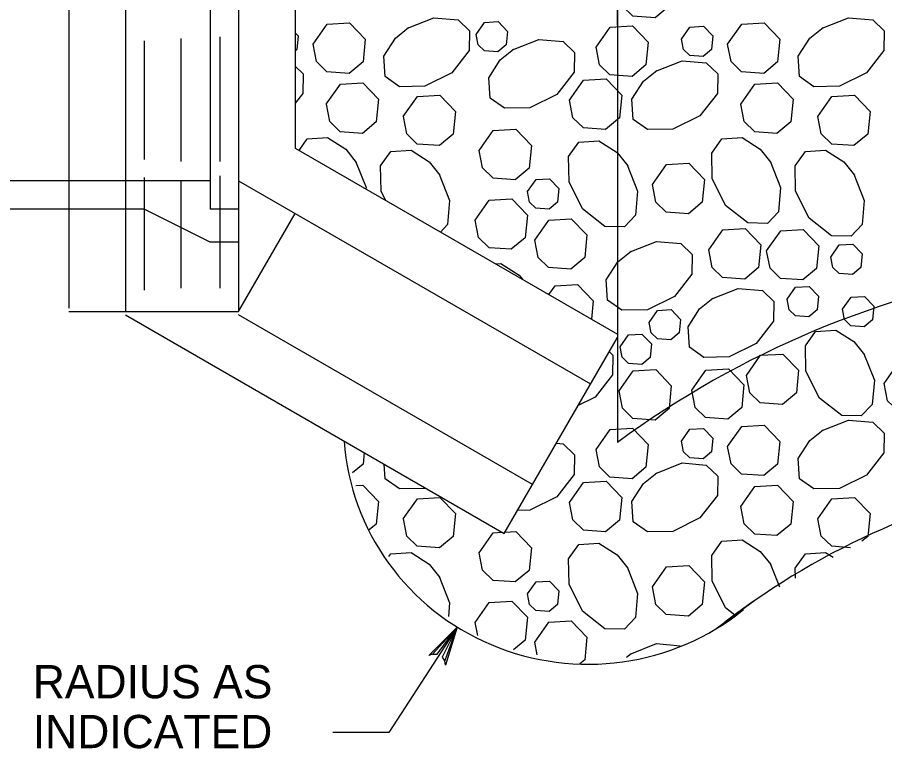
# Model space of a CAD drawing. Extents: x 636183 to 639890, y 299162 to 300538.
# Drawn here: x 638288.4 to 638366.6, y 299728.5 to 299794.5 of the extents above; entities that cross this region are included whole.
import ezdxf

# ---------------------------------------------------------------- set-up
doc = ezdxf.new("R2010")
doc.units = 0
doc.layers.add('Default', color=7, linetype='Continuous')

msp = doc.modelspace()

# ---------------------------------------------------------------- linework, layer by layer
at = {"layer": 'Default'}
for p, q in [((638342.479, 299793.775), (638342.479, 299831.402)), ((638342.479, 299821.642), (638342.479, 299765.907)), ((638293.003, 299819.284), (638293.003, 299768.259)), ((638298.106, 299819.586), (638298.106, 299767.957)), ((638308.311, 299819.586), (638308.311, 299767.957)), ((638308.311, 299813.345), (638308.311, 299774.198)), ((638305.757, 299810.356), (638305.757, 299777.187)), ((638313.413, 299804.859), (638313.413, 299782.689)), ((638342.479, 299793.775), (638342.479, 299756.147)), ((638306.61, 299792.726), (638306.61, 299781.487)), ((638299.806, 299792.377), (638299.806, 299781.65)), ((638303.111, 299792.563), (638303.111, 299781.487)), ((638313.413, 299782.689), (638342.479, 299765.907)), ((638306.61, 299780.185), (638306.61, 299770.064)), ((638305.757, 299779.741), (638263.016, 299779.741)), ((638299.806, 299780.045), (638299.806, 299769.878)), ((638303.111, 299779.766), (638303.111, 299770.064)), ((638308.311, 299779.741), (638340.059, 299761.414)), ((638298.106, 299777.187), (638261.142, 299777.187)), ((638299.779, 299777.187), (638298.106, 299777.187)), ((638305.757, 299774.198), (638299.779, 299777.187)), ((638308.311, 299777.187), (638305.757, 299777.187)), ((638308.311, 299767.957), (638313.413, 299776.795)), ((638308.311, 299774.198), (638305.757, 299774.198)), ((638293.003, 299767.957), (638308.311, 299767.957)), ((638298.106, 299767.656), (638332.272, 299747.931)), ((638334.823, 299752.348), (638308.311, 299767.656)), ((638332.272, 299747.931), (638342.479, 299765.606)), ((638354.872, 299741.885), (638351.469, 299739.382))]:
    msp.add_line(p, q, dxfattribs=at)
for points in [[(638342.633, 299797.075), (638343.904, 299798.882), (638345.933, 299798.998), (638347.342, 299797.536), (638347.138, 299795.487), (638345.885, 299794.445), (638343.882, 299794.59), (638342.94, 299795.504), (638342.635, 299797.074)], [(638323.553, 299793.503), (638325.931, 299794.445), (638328.114, 299794.257), (638329.151, 299793.27), (638329.119, 299791.498), (638327.544, 299789.485), (638325.11, 299788.268), (638322.815, 299788.228), (638321.525, 299789.146), (638321.402, 299790.972), (638322.45, 299792.607), (638323.65, 299793.564)], [(638360.947, 299793.503), (638363.325, 299794.445), (638365.507, 299794.257), (638366.545, 299793.27), (638366.513, 299791.498), (638364.938, 299789.485), (638362.504, 299788.268), (638360.209, 299788.228), (638358.919, 299789.146), (638358.796, 299790.972), (638359.844, 299792.607), (638361.044, 299793.564)], [(638315.028, 299792.058), (638316.298, 299793.865), (638318.327, 299793.981), (638319.737, 299792.519), (638319.533, 299790.47), (638318.28, 299789.428), (638316.278, 299789.573), (638315.335, 299790.486), (638315.029, 299792.058)], [(638329.73, 299792.943), (638330.493, 299794.028), (638331.71, 299794.097), (638332.556, 299793.22), (638332.434, 299791.991), (638331.682, 299791.365), (638330.48, 299791.452), (638329.915, 299792.001), (638329.731, 299792.943)], [(638340.55, 299791.783), (638341.82, 299793.59), (638343.848, 299793.707), (638345.259, 299792.244), (638345.055, 299790.195), (638343.802, 299789.153), (638341.799, 299789.299), (638340.857, 299790.212), (638340.55, 299791.783)], [(638348.258, 299792.526), (638349.021, 299793.61), (638350.238, 299793.68), (638351.084, 299792.802), (638350.961, 299791.574), (638350.21, 299790.948), (638349.007, 299791.035), (638348.442, 299791.583), (638348.259, 299792.526)], [(638352.422, 299792.058), (638353.692, 299793.865), (638355.721, 299793.981), (638357.131, 299792.519), (638356.927, 299790.47), (638355.674, 299789.428), (638353.671, 299789.573), (638352.728, 299790.486), (638352.423, 299792.058)], [(638313.413, 299793.09), (638313.69, 299792.802), (638313.568, 299791.574), (638313.413, 299791.445)], [(638333.022, 299791.551), (638335.399, 299792.493), (638337.582, 299792.305), (638338.62, 299791.319), (638338.587, 299789.547), (638337.012, 299787.534), (638334.579, 299786.317), (638332.284, 299786.277), (638330.994, 299787.194), (638330.871, 299789.021), (638331.919, 299790.656), (638333.119, 299791.613)], [(638345.935, 299789.63), (638348.311, 299790.572), (638350.495, 299790.383), (638351.532, 299789.397), (638351.499, 299787.625), (638349.924, 299785.613), (638347.49, 299784.396), (638345.197, 299784.355), (638343.905, 299785.272), (638343.783, 299787.1), (638344.831, 299788.734), (638346.031, 299789.691)], [(638313.413, 299790.087), (638314.138, 299789.397), (638314.105, 299787.625), (638313.413, 299786.741)], [(638338.159, 299787.002), (638339.43, 299788.809), (638341.458, 299788.925), (638342.868, 299787.463), (638342.664, 299785.414), (638341.411, 299784.372), (638339.408, 299784.517), (638338.466, 299785.431), (638338.16, 299787.002)], [(638316.224, 299786.647), (638317.494, 299788.455), (638319.522, 299788.57), (638320.932, 299787.108), (638320.728, 299785.06), (638319.475, 299784.018), (638317.473, 299784.162), (638316.531, 299785.076), (638316.225, 299786.647)], [(638353.618, 299786.647), (638354.888, 299788.455), (638356.916, 299788.57), (638358.326, 299787.108), (638358.122, 299785.06), (638356.869, 299784.018), (638354.867, 299784.162), (638353.925, 299785.076), (638353.619, 299786.647)], [(638323.17, 299785.541), (638324.44, 299787.347), (638326.468, 299787.464), (638327.878, 299786.002), (638327.674, 299783.953), (638326.421, 299782.91), (638324.419, 299783.056), (638323.477, 299783.969), (638323.171, 299785.54)], [(638360.564, 299785.541), (638361.834, 299787.347), (638363.862, 299787.464), (638365.272, 299786.002), (638365.068, 299783.953), (638363.815, 299782.91), (638361.813, 299783.056), (638360.871, 299783.969), (638360.565, 299785.54)], [(638330.012, 299782.467), (638331.283, 299784.275), (638333.311, 299784.39), (638334.721, 299782.928), (638334.517, 299780.88), (638333.264, 299779.837), (638331.261, 299779.982), (638330.319, 299780.897), (638330.013, 299782.467)], [(638313.768, 299782.484), (638314.51, 299783.528), (638316.337, 299783.65), (638317.971, 299782.603), (638318.928, 299781.403)], [(638343.348, 299781.191), (638344.291, 299778.815), (638344.102, 299776.631), (638343.116, 299775.593), (638341.344, 299775.627), (638339.332, 299777.201), (638338.114, 299779.635), (638338.074, 299781.929), (638338.991, 299783.22), (638340.819, 299783.342), (638342.453, 299782.295), (638343.41, 299781.095)], [(638356.261, 299781.498), (638357.204, 299779.122), (638357.015, 299776.938), (638356.028, 299775.901), (638354.256, 299775.934), (638352.244, 299777.509), (638351.027, 299779.943), (638350.986, 299782.236), (638351.904, 299783.528), (638353.731, 299783.65), (638355.365, 299782.603), (638356.322, 299781.403)], [(638321.571, 299777.979), (638321.166, 299778.79), (638321.125, 299781.084), (638322.043, 299782.375), (638323.869, 299782.497), (638325.504, 299781.45), (638326.461, 299780.25)], [(638363.793, 299780.346), (638364.735, 299777.969), (638364.547, 299775.786), (638363.561, 299774.748), (638361.789, 299774.781), (638359.776, 299776.356), (638358.559, 299778.79), (638358.519, 299781.084), (638359.436, 299782.375), (638361.263, 299782.497), (638362.898, 299781.45), (638363.855, 299780.25)], [(638318.868, 299781.498), (638319.81, 299779.122), (638319.799, 299779.002)], [(638345.631, 299779.393), (638346.901, 299781.201), (638348.93, 299781.316), (638350.341, 299779.854), (638350.137, 299777.806), (638348.884, 299776.764), (638346.88, 299776.908), (638345.938, 299777.822), (638345.632, 299779.393)], [(638326.4, 299780.346), (638327.342, 299777.969), (638327.154, 299775.786), (638326.522, 299775.121)], [(638334.377, 299778.764), (638335.14, 299779.849), (638336.357, 299779.919), (638337.203, 299779.041), (638337.081, 299777.811), (638336.329, 299777.186), (638335.127, 299777.274), (638334.562, 299777.822), (638334.378, 299778.764)], [(638329.657, 299776.192), (638330.927, 299777.999), (638332.955, 299778.115), (638334.365, 299776.653), (638334.161, 299774.603), (638332.908, 299773.561), (638330.905, 299773.707), (638329.963, 299774.62), (638329.658, 299776.191)], [(638335.025, 299774.397), (638336.296, 299776.204), (638338.323, 299776.32), (638339.734, 299774.859), (638339.53, 299772.809), (638338.277, 299771.767), (638336.274, 299771.912), (638335.332, 299772.826), (638335.026, 299774.397)], [(638350.716, 299773.502), (638351.986, 299775.309), (638354.014, 299775.425), (638355.424, 299773.963), (638355.22, 299771.914), (638353.967, 299770.872), (638351.965, 299771.017), (638351.023, 299771.93), (638350.717, 299773.501)], [(638355.942, 299773.424), (638357.212, 299775.232), (638359.241, 299775.348), (638360.651, 299773.885), (638360.447, 299771.837), (638359.194, 299770.795), (638357.191, 299770.94), (638356.249, 299771.854), (638355.943, 299773.424)], [(638343.629, 299773.336), (638346.005, 299774.278), (638348.189, 299774.089), (638349.227, 299773.103), (638349.194, 299771.331), (638347.618, 299769.319), (638345.184, 299768.102), (638342.891, 299768.061), (638341.599, 299768.978), (638341.477, 299770.806), (638342.525, 299772.44), (638343.724, 299773.397)], [(638361.723, 299772.867), (638362.485, 299773.951), (638363.703, 299774.02), (638364.548, 299773.143), (638364.425, 299771.914), (638363.674, 299771.289), (638362.472, 299771.376), (638361.906, 299771.924), (638361.723, 299772.866)], [(638331.505, 299772.243), (638331.98, 299772.275), (638333.614, 299771.227), (638333.912, 299770.854)], [(638336.307, 299769.471), (638336.861, 299770.259), (638338.889, 299770.374), (638340.299, 299768.912), (638340.135, 299767.261)], [(638351.002, 299769.091), (638353.379, 299770.033), (638355.562, 299769.844), (638356.601, 299768.857), (638356.568, 299767.086), (638354.992, 299765.072), (638352.558, 299763.856), (638350.265, 299763.815), (638348.973, 299764.733), (638348.851, 299766.56), (638349.898, 299768.194), (638351.098, 299769.151)], [(638357.79, 299769.053), (638358.553, 299770.138), (638359.77, 299770.208), (638360.616, 299769.33), (638360.494, 299768.101), (638359.742, 299767.475), (638358.54, 299767.563), (638357.975, 299768.111), (638357.791, 299769.053)], [(638362.795, 299768.16), (638363.557, 299769.244), (638364.774, 299769.314), (638365.621, 299768.436), (638365.498, 299767.208), (638364.747, 299766.582), (638363.545, 299766.669), (638362.979, 299767.217), (638362.795, 299768.159)], [(638345.339, 299766.969), (638346.102, 299768.053), (638347.319, 299768.122), (638348.165, 299767.245), (638348.043, 299766.016), (638347.29, 299765.391), (638346.089, 299765.478), (638345.524, 299766.026), (638345.34, 299766.969)], [(638364.715, 299764.128), (638365.658, 299761.752), (638365.469, 299759.568), (638364.482, 299758.531), (638362.71, 299758.564), (638360.697, 299760.139), (638359.481, 299762.573), (638359.44, 299764.866), (638360.358, 299766.158), (638362.185, 299766.28), (638363.819, 299765.233), (638364.776, 299764.033)], [(638342.718, 299764.764), (638343.481, 299765.849), (638344.698, 299765.918), (638345.543, 299765.041), (638345.421, 299763.812), (638344.669, 299763.186), (638343.467, 299763.273), (638342.902, 299763.821), (638342.719, 299764.764)], [(638341.743, 299764.332), (638342.076, 299764.016), (638342.042, 299762.244), (638340.467, 299760.231), (638338.932, 299759.463)], [(638354.116, 299762.192), (638355.386, 299764), (638357.414, 299764.116), (638358.825, 299762.653), (638358.621, 299760.605), (638357.367, 299759.562), (638355.365, 299759.708), (638354.423, 299760.622), (638354.117, 299762.192)], [(638366.545, 299761.463), (638367.816, 299763.27), (638369.845, 299763.386), (638371.254, 299761.924), (638371.05, 299759.875), (638369.797, 299758.833), (638367.794, 299758.978), (638366.852, 299759.891), (638366.547, 299761.463)], [(638342.633, 299760.793), (638343.904, 299762.599), (638345.933, 299762.716), (638347.342, 299761.254), (638347.138, 299759.204), (638345.885, 299758.162), (638343.882, 299758.308), (638342.94, 299759.221), (638342.635, 299760.792)], [(638349.188, 299760.867), (638350.459, 299762.674), (638352.487, 299762.79), (638353.897, 299761.328), (638353.693, 299759.279), (638352.44, 299758.237), (638350.437, 299758.382), (638349.495, 299759.296), (638349.19, 299760.866)], [(638352.422, 299755.775), (638353.692, 299757.583), (638355.721, 299757.698), (638357.131, 299756.236), (638356.927, 299754.188), (638355.674, 299753.146), (638353.671, 299753.29), (638352.728, 299754.204), (638352.423, 299755.775)], [(638360.947, 299757.22), (638363.325, 299758.162), (638365.507, 299757.974), (638366.545, 299756.988), (638366.513, 299755.216), (638364.938, 299753.202), (638362.504, 299751.985), (638360.209, 299751.946), (638358.919, 299752.863), (638358.796, 299754.69), (638359.844, 299756.324), (638361.044, 299757.281)], [(638340.55, 299755.5), (638341.82, 299757.308), (638343.848, 299757.424), (638345.259, 299755.961), (638345.055, 299753.913), (638343.802, 299752.871), (638341.799, 299753.016), (638340.857, 299753.93), (638340.55, 299755.5)], [(638348.258, 299756.244), (638349.021, 299757.328), (638350.238, 299757.398), (638351.084, 299756.52), (638350.961, 299755.291), (638350.21, 299754.666), (638349.007, 299754.753), (638348.442, 299755.301), (638348.259, 299756.243)], [(638336.975, 299756.075), (638337.582, 299756.023), (638338.62, 299755.036), (638338.587, 299753.265), (638337.012, 299751.251), (638334.579, 299750.034), (638333.475, 299750.015)], [(638319.636, 299755.226), (638319.533, 299754.188), (638318.589, 299753.403)], [(638325.184, 299752.023), (638325.11, 299751.985), (638322.815, 299751.946), (638321.525, 299752.863), (638321.436, 299754.187)], [(638345.935, 299753.348), (638348.311, 299754.29), (638350.495, 299754.101), (638351.532, 299753.114), (638351.499, 299751.343), (638349.924, 299749.33), (638347.49, 299748.113), (638345.197, 299748.072), (638343.905, 299748.99), (638343.783, 299750.817), (638344.831, 299752.451), (638346.031, 299753.408)], [(638318.891, 299752.252), (638319.522, 299752.288), (638320.932, 299750.826), (638320.728, 299748.777), (638320.102, 299748.256)], [(638338.159, 299750.719), (638339.43, 299752.527), (638341.458, 299752.643), (638342.868, 299751.18), (638342.664, 299749.132), (638341.411, 299748.089), (638339.408, 299748.235), (638338.466, 299749.149), (638338.16, 299750.719)], [(638353.618, 299750.365), (638354.888, 299752.172), (638356.916, 299752.288), (638358.326, 299750.826), (638358.122, 299748.777), (638356.869, 299747.735), (638354.867, 299747.88), (638353.925, 299748.793), (638353.619, 299750.365)], [(638323.17, 299749.258), (638324.44, 299751.065), (638326.468, 299751.181), (638327.878, 299749.719), (638327.674, 299747.671), (638326.421, 299746.628), (638324.419, 299746.773), (638323.477, 299747.687), (638323.171, 299749.257)], [(638360.564, 299749.258), (638361.834, 299751.065), (638363.862, 299751.181), (638365.272, 299749.719), (638365.068, 299747.671), (638364.53, 299747.223)], [(638363.495, 299746.651), (638361.813, 299746.773), (638360.871, 299747.687), (638360.565, 299749.257)], [(638332.342, 299748.052), (638333.311, 299748.107), (638334.721, 299746.646), (638334.517, 299744.597), (638333.264, 299743.555), (638331.261, 299743.699), (638330.319, 299744.614), (638330.013, 299746.184)], [(638330.012, 299746.184), (638331.283, 299747.992), (638332.087, 299748.038)], [(638353.083, 299740.569), (638352.244, 299741.226), (638351.027, 299743.661), (638350.986, 299745.954), (638351.904, 299747.246), (638353.731, 299747.367), (638355.365, 299746.32), (638356.322, 299745.12)], [(638343.348, 299744.909), (638344.291, 299742.532), (638344.102, 299740.349), (638343.116, 299739.31), (638341.344, 299739.344), (638339.332, 299740.918), (638338.114, 299743.353), (638338.074, 299745.647), (638338.991, 299746.937), (638340.819, 299747.059), (638342.453, 299746.012), (638343.41, 299744.812)], [(638321.864, 299745.842), (638322.043, 299746.093), (638323.869, 299746.215), (638325.504, 299745.168), (638326.461, 299743.968)], [(638358.535, 299743.909), (638358.519, 299744.801), (638359.436, 299746.093), (638361.263, 299746.215), (638361.931, 299745.787)], [(638345.631, 299743.111), (638346.901, 299744.918), (638348.93, 299745.034), (638350.341, 299743.572), (638350.137, 299741.523), (638348.884, 299740.481), (638346.88, 299740.626), (638345.938, 299741.539), (638345.632, 299743.111)], [(638356.261, 299745.216), (638357.095, 299743.113)], [(638326.4, 299744.063), (638327.342, 299741.687), (638327.234, 299740.438)], [(638334.377, 299742.481), (638335.14, 299743.566), (638336.357, 299743.636), (638337.203, 299742.758), (638337.081, 299741.529), (638336.329, 299740.903), (638335.127, 299740.991), (638334.562, 299741.539), (638334.378, 299742.481)], [(638329.657, 299739.909), (638330.927, 299741.716), (638332.955, 299741.832), (638334.365, 299740.37), (638334.161, 299738.321), (638333.102, 299737.44)], [(638328.026, 299739.494), (638321.856, 299729.985), (638316.825, 299729.985)], [(638325.812, 299737.055), (638325.482, 299736.94), (638328.026, 299739.494), (638325.812, 299737.055), (638326.233, 299737.031), (638328.026, 299739.494), (638326.684, 299736.766), (638326.912, 299736.416), (638328.026, 299739.494), (638326.983, 299736.043), (638326.912, 299736.416)], [(638329.886, 299738.731), (638329.658, 299739.908)], [(638335.025, 299738.115), (638336.296, 299739.922), (638338.323, 299740.038), (638339.734, 299738.576), (638339.53, 299736.526), (638339.101, 299736.17)], [(638335.245, 299736.986), (638335.026, 299738.114)], [(638343.629, 299737.054), (638346.005, 299737.996), (638348.127, 299737.812)], [(638343.302, 299736.777), (638343.724, 299737.114)]]:
    msp.add_lwpolyline(points, dxfattribs=at)
for centre, major_axis, ratio, start_param, end_param in [((638390.958, 299657.201), (0, 115.259), 0.820107, 0.123497, 0.538521), ((638339.839, 299757.697), (22.048, 0), 0.97775, 3.208138, 5.401998), ((638390.958, 299657.201), (0, 96.361), 0.784827, 0.123497, 0.538521)]:
    msp.add_ellipse(centre, major_axis=major_axis, ratio=ratio, start_param=start_param, end_param=end_param, dxfattribs=at)

# ---------------------------------------------------------------- texts
for s, p in [('RADIUS AS', (638289.747, 299733.064)), ('INDICATED', (638289.747, 299728.567))]:
    msp.add_text(s, height=2.998, dxfattribs=at).set_placement(p)

doc.saveas('drawing.dxf')
